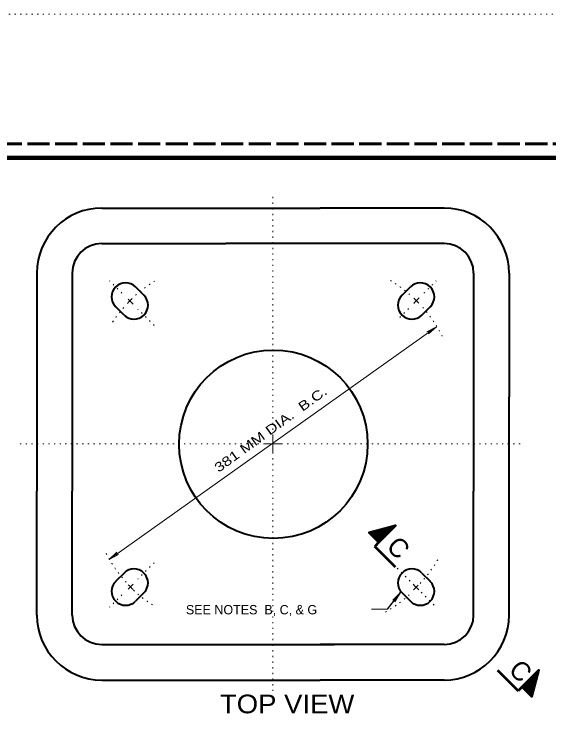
# Model space of a CAD drawing. Extents: x 312583 to 312854, y 144419 to 144597.
# Drawn here: x 312713.9 to 312757.4, y 144539.3 to 144596.8 of the extents above; entities that cross this region are included whole.
import ezdxf
from ezdxf.enums import TextEntityAlignment as Align

# ---------------------------------------------------------------- set-up
doc = ezdxf.new("R2010")
doc.units = 0
doc.header["$LTSCALE"] = 0.3
doc.linetypes.add('DOTTED', pattern=[1.5, 0.3, -1.2])
doc.linetypes.add('LONG_DASHED', pattern=[7.5, 6, -1.5])
for name, color, linetype, lineweight in [('1', 7, 'Continuous', 40), ('2', 7, 'Continuous', 13), ('62', 7, 'DOTTED', 13), ('63', 7, 'LONG_DASHED', 60)]:
    doc.layers.add(name, color=color, linetype=linetype, lineweight=lineweight)

msp = doc.modelspace()

# ---------------------------------------------------------------- linework, layer by layer
at = {"layer": '1'}
for p, q in [((312721.0029, 144581.0012), (312738.7589, 144581.0012)), ((312748.8483, 144581.0012), (312738.7589, 144581.0012)), ((312721.0029, 144578.1186), (312731.0923, 144578.1186)), ((312748.8483, 144578.1186), (312731.0923, 144578.1186)), ((312715.7206, 144575.7112), (312715.7206, 144557.9629)), ((312718.6033, 144575.7112), (312718.6033, 144557.9629)), ((312751.2479, 144575.7112), (312751.2479, 144557.9629)), ((312754.1306, 144575.7112), (312754.1306, 144565.6296)), ((312724.4299, 144573.9096), (312723.7476, 144574.5842)), ((312745.4289, 144573.9096), (312746.1036, 144574.5842)), ((312722.8123, 144572.2919), (312722.1376, 144572.9666)), ((312747.0389, 144572.2919), (312747.7213, 144572.9666)), ((312754.1306, 144547.8736), (312754.1306, 144565.6296)), ((312715.7206, 144547.8736), (312715.7206, 144557.9629)), ((312718.6033, 144547.8736), (312718.6033, 144557.9629)), ((312751.2479, 144547.8736), (312751.2479, 144557.9629)), ((312722.8123, 144551.2929), (312722.1376, 144550.6182)), ((312747.0389, 144551.2929), (312747.7213, 144550.6182)), ((312724.4299, 144549.6829), (312723.7476, 144549.0006)), ((312745.4289, 144549.6829), (312746.1036, 144549.0006)), ((312721.0029, 144545.4662), (312739.9396, 144545.4662)), ((312748.8483, 144545.4662), (312738.7589, 144545.4662)), ((312721.0029, 144542.5836), (312738.7589, 144542.5836)), ((312748.8483, 144542.5836), (312738.7589, 144542.5836))]:
    msp.add_line(p, q, dxfattribs=at)
at = {"layer": '1', "linetype": 'DOTTED', "lineweight": 13}
for p, q in [((312722.6436, 144574.0782), (312721.6393, 144575.0749)), ((312747.1999, 144574.0629), (312748.2119, 144575.0749)), ((312746.3719, 144573.2349), (312746.8703, 144573.7409)), ((312745.2373, 144572.1002), (312746.1189, 144572.9819)), ((312725.2733, 144571.4486), (312723.9316, 144572.7826)), ((312725.2733, 144552.1362), (312723.9316, 144550.8022)), ((312745.0379, 144551.6839), (312748.2119, 144548.5099)), ((312722.6436, 144549.5066), (312721.6393, 144548.5099))]:
    msp.add_line(p, q, dxfattribs=at)
at = {"layer": '1', "lineweight": 13}
for p, q in [((312723.5483, 144573.1736), (312723.1419, 144573.5799)), ((312746.4103, 144573.2809), (312746.8243, 144573.6872)), ((312723.5483, 144550.3882), (312723.1419, 144549.9819)), ((312746.3796, 144550.3192), (312746.7859, 144549.9129))]:
    msp.add_line(p, q, dxfattribs=at)
at = {"layer": '1', "lineweight": 35}
for p, q in [((312744.6929, 144554.9422), (312744.6469, 144555.0879)), ((312744.7083, 144554.9576), (312744.6776, 144555.0956)), ((312744.7236, 144554.9806), (312744.6929, 144555.0956)), ((312744.7466, 144554.9959), (312744.7236, 144555.1032)), ((312744.7696, 144555.0189), (312744.7389, 144555.1109)), ((312744.7926, 144555.0419), (312744.7696, 144555.1186)), ((312744.8079, 144555.0572), (312744.7849, 144555.1186)), ((312744.8233, 144555.0802), (312744.8079, 144555.1339)), ((312744.8463, 144555.0956), (312744.8309, 144555.1416)), ((312744.8693, 144555.1186), (312744.8539, 144555.1416)), ((312744.8923, 144555.1339), (312744.8769, 144555.1492)), ((312742.7763, 144554.5589), (312742.7763, 144554.5819)), ((312742.8146, 144554.5282), (312742.7993, 144554.5896)), ((312742.8529, 144554.4899), (312742.8299, 144554.5896)), ((312742.8836, 144554.4516), (312742.8529, 144554.5972)), ((312742.9219, 144554.4209), (312742.8683, 144554.6049)), ((312742.9449, 144554.3902), (312742.8913, 144554.6049)), ((312742.9909, 144554.3519), (312742.9143, 144554.6202)), ((312743.0216, 144554.3212), (312742.9449, 144554.6279)), ((312743.0523, 144554.2906), (312742.9603, 144554.6356)), ((312743.0829, 144554.2599), (312742.9909, 144554.6432)), ((312743.1213, 144554.2139), (312743.0063, 144554.6432)), ((312743.1519, 144554.1832), (312743.0369, 144554.6509)), ((312743.1826, 144554.1526), (312743.0523, 144554.6586)), ((312743.2286, 144554.1142), (312743.0753, 144554.6586)), ((312743.2593, 144554.0836), (312743.0983, 144554.6739)), ((312743.2899, 144554.0529), (312743.1136, 144554.6739)), ((312743.3283, 144554.0069), (312743.1443, 144554.6739)), ((312743.3589, 144553.9839), (312743.1749, 144554.6892)), ((312743.3973, 144553.9456), (312743.1903, 144554.6892)), ((312743.4203, 144553.9149), (312743.2133, 144554.6969)), ((312743.4586, 144553.8766), (312743.2439, 144554.7046)), ((312743.4893, 144553.8459), (312743.2593, 144554.7046)), ((312743.5276, 144553.8152), (312743.2899, 144554.7199)), ((312743.5506, 144553.8076), (312743.3053, 144554.7199)), ((312743.5736, 144553.8306), (312743.3359, 144554.7352)), ((312743.5966, 144553.8459), (312743.3589, 144554.7352)), ((312743.6119, 144553.8612), (312743.3743, 144554.7429)), ((312743.6349, 144553.8842), (312743.3973, 144554.7429)), ((312743.6426, 144553.9072), (312743.4279, 144554.7582)), ((312743.6733, 144553.9302), (312743.4509, 144554.7582)), ((312743.6886, 144553.9456), (312743.4663, 144554.7736)), ((312743.7116, 144553.9609), (312743.4969, 144554.7736)), ((312743.7346, 144553.9839), (312743.5199, 144554.7736)), ((312743.7499, 144553.9992), (312743.5353, 144554.7889)), ((312743.7729, 144554.0222), (312743.5659, 144554.7889)), ((312743.7883, 144554.0452), (312743.5889, 144554.7966)), ((312743.8036, 144554.0606), (312743.6119, 144554.8042)), ((312743.8266, 144554.0836), (312743.6349, 144554.8042)), ((312743.8496, 144554.1066), (312743.6579, 144554.8196)), ((312743.8649, 144554.1219), (312743.6809, 144554.8196)), ((312743.8879, 144554.1372), (312743.7039, 144554.8272)), ((312743.9033, 144554.1602), (312743.7346, 144554.8349)), ((312743.9263, 144554.1756), (312743.7423, 144554.8426)), ((312743.9493, 144554.2062), (312743.7729, 144554.8502)), ((312743.9646, 144554.2216), (312743.7959, 144554.8579)), ((312743.9876, 144554.2369), (312743.8113, 144554.8579)), ((312744.0029, 144554.2599), (312743.8419, 144554.8732)), ((312744.0259, 144554.2752), (312743.8649, 144554.8732)), ((312744.0413, 144554.2906), (312743.8879, 144554.8809)), ((312744.0566, 144554.3136), (312743.9109, 144554.8886)), ((312744.0873, 144554.3366), (312743.9339, 144554.8886)), ((312744.1026, 144554.3519), (312743.9569, 144554.8962)), ((312744.1179, 144554.3749), (312743.9799, 144554.9039)), ((312744.1409, 144554.3979), (312744.0029, 144554.9116)), ((312744.1563, 144554.4132), (312744.0259, 144554.9116)), ((312744.1869, 144554.4362), (312744.0489, 144554.9269)), ((312744.2023, 144554.4516), (312744.0719, 144554.9269)), ((312744.2176, 144554.4746), (312744.0949, 144554.9346)), ((312744.2329, 144554.4899), (312744.1179, 144554.9499)), ((312744.2636, 144554.5129), (312744.1409, 144554.9576)), ((312744.2789, 144554.5282), (312744.1639, 144554.9576)), ((312744.3019, 144554.5589), (312744.1869, 144554.9576)), ((312744.3173, 144554.5666), (312744.2099, 144554.9729)), ((312744.3403, 144554.5896), (312744.2329, 144554.9652)), ((312744.3556, 144554.6126), (312744.2636, 144554.9729)), ((312744.3786, 144554.6279), (312744.2789, 144554.9882)), ((312744.3939, 144554.6432), (312744.3019, 144554.9882)), ((312744.4169, 144554.6662), (312744.3249, 144554.9959)), ((312744.4399, 144554.6892), (312744.3556, 144555.0036)), ((312744.4553, 144554.7046), (312744.3633, 144555.0112)), ((312744.4706, 144554.7276), (312744.4016, 144555.0189)), ((312744.4936, 144554.7429), (312744.4169, 144555.0266)), ((312744.5166, 144554.7659), (312744.4399, 144555.0342)), ((312744.5319, 144554.7889), (312744.4629, 144555.0419)), ((312744.5549, 144554.8042), (312744.4859, 144555.0419)), ((312744.5703, 144554.8196), (312744.5089, 144555.0496)), ((312744.5933, 144554.8426), (312744.5319, 144555.0572)), ((312744.6086, 144554.8656), (312744.5549, 144555.0572)), ((312744.6316, 144554.8886), (312744.5779, 144555.0649)), ((312744.6623, 144554.9039), (312744.6086, 144555.0726)), ((312744.6699, 144554.9192), (312744.6239, 144555.0726)), ((312756.2006, 144543.0282), (312756.4536, 144542.9592)), ((312756.2159, 144543.0436), (312756.4536, 144542.9822)), ((312756.2389, 144543.0666), (312756.4613, 144543.0052)), ((312756.2543, 144543.0819), (312756.4689, 144543.0282)), ((312756.2773, 144543.1049), (312756.4689, 144543.0512)), ((312756.2926, 144543.1279), (312756.4766, 144543.0742)), ((312756.3156, 144543.1509), (312756.4843, 144543.0972)), ((312756.3309, 144543.1662), (312756.4843, 144543.1202)), ((312756.3539, 144543.1892), (312756.4919, 144543.1432)), ((312756.3693, 144543.2046), (312756.4996, 144543.1739)), ((312756.3846, 144543.2199), (312756.5149, 144543.1892)), ((312756.4076, 144543.2429), (312756.5149, 144543.2122)), ((312756.4306, 144543.2659), (312756.5226, 144543.2352)), ((312756.4536, 144543.2812), (312756.5303, 144543.2659)), ((312756.4689, 144543.3042), (312756.5379, 144543.2812)), ((312756.4919, 144543.3196), (312756.5379, 144543.3042)), ((312756.5073, 144543.3349), (312756.5533, 144543.3272)), ((312756.5303, 144543.3579), (312756.5533, 144543.3502)), ((312756.5533, 144543.3809), (312756.5609, 144543.3732)), ((312755.6103, 144542.4456), (312756.2543, 144542.2616)), ((312755.6256, 144542.4609), (312756.2696, 144542.2846)), ((312755.6486, 144542.4839), (312756.2696, 144542.3076)), ((312755.6716, 144542.4916), (312756.2849, 144542.3382)), ((312755.6869, 144542.5222), (312756.2849, 144542.3536)), ((312755.7023, 144542.5376), (312756.2926, 144542.3842)), ((312755.7253, 144542.5606), (312756.3003, 144542.4072)), ((312755.7483, 144542.5759), (312756.3003, 144542.4302)), ((312755.7636, 144542.5989), (312756.3079, 144542.4532)), ((312755.7866, 144542.6142), (312756.3156, 144542.4762)), ((312755.8096, 144542.6372), (312756.3233, 144542.4916)), ((312755.8249, 144542.6526), (312756.3309, 144542.5222)), ((312755.8479, 144542.6756), (312756.3386, 144542.5452)), ((312755.8633, 144542.6986), (312756.3386, 144542.5606)), ((312755.8863, 144542.7139), (312756.3463, 144542.5836)), ((312755.9016, 144542.7292), (312756.3539, 144542.6142)), ((312755.9246, 144542.7522), (312756.3616, 144542.6372)), ((312755.9399, 144542.7752), (312756.3693, 144542.6526)), ((312755.9629, 144542.7982), (312756.3693, 144542.6832)), ((312755.9783, 144542.8136), (312756.3846, 144542.7062)), ((312756.0013, 144542.8366), (312756.3846, 144542.7292)), ((312756.0166, 144542.8519), (312756.3846, 144542.7522)), ((312756.0396, 144542.8749), (312756.3999, 144542.7752)), ((312756.0549, 144542.8902), (312756.3999, 144542.7982)), ((312756.0779, 144542.9132), (312756.4076, 144542.8212)), ((312756.1009, 144542.9286), (312756.4153, 144542.8442)), ((312756.1163, 144542.9516), (312756.4229, 144542.8596)), ((312756.1393, 144542.9669), (312756.4306, 144542.8902)), ((312756.1546, 144542.9899), (312756.4383, 144542.9132)), ((312756.1776, 144543.0052), (312756.4383, 144542.9362)), ((312755.2193, 144542.0469), (312756.1316, 144541.8016)), ((312755.2193, 144542.0239), (312756.1316, 144541.7862)), ((312755.2346, 144542.0699), (312756.1469, 144541.8246)), ((312755.2576, 144542.0929), (312756.1469, 144541.8552)), ((312755.2576, 144541.9856), (312756.1163, 144541.7556)), ((312755.2729, 144542.1082), (312756.1546, 144541.8706)), ((312755.2883, 144541.9549), (312756.1163, 144541.7326)), ((312755.2959, 144542.1312), (312756.1623, 144541.8936)), ((312755.3189, 144542.1389), (312756.1699, 144541.9166)), ((312755.3266, 144541.9166), (312756.1086, 144541.7096)), ((312755.3419, 144542.1619), (312756.1699, 144541.9396)), ((312755.3496, 144542.1849), (312756.1776, 144541.9626)), ((312755.3573, 144541.8859), (312756.1009, 144541.6866)), ((312755.3726, 144542.2079), (312756.1853, 144541.9856)), ((312755.3956, 144542.2309), (312756.1853, 144542.0086)), ((312755.4109, 144542.2462), (312756.2006, 144542.0316)), ((312755.4339, 144542.2616), (312756.2006, 144542.0622)), ((312755.4569, 144542.2846), (312756.2083, 144542.0852)), ((312755.4723, 144542.2999), (312756.2159, 144542.1006)), ((312755.4953, 144542.3229), (312756.2159, 144542.1312)), ((312755.5183, 144542.3459), (312756.2313, 144542.1542)), ((312755.5336, 144542.3612), (312756.2313, 144542.1696)), ((312755.5489, 144542.3766), (312756.2389, 144542.1926)), ((312755.5719, 144542.3996), (312756.2466, 144542.2232)), ((312755.5873, 144542.4226), (312756.2543, 144542.2386)), ((312755.3879, 144541.8552), (312756.1009, 144541.6636)), ((312755.4186, 144541.8169), (312756.0933, 144541.6406)), ((312755.4569, 144541.7862), (312756.0856, 144541.6176)), ((312755.4953, 144541.7479), (312756.0856, 144541.5946)), ((312755.5259, 144541.7172), (312756.0703, 144541.5716)), ((312755.5643, 144541.6789), (312756.0703, 144541.5486)), ((312755.5949, 144541.6482), (312756.0626, 144541.5256)), ((312755.6256, 144541.6176), (312756.0549, 144541.5026)), ((312755.6639, 144541.5792), (312756.0549, 144541.4872)), ((312755.7023, 144541.5409), (312756.0396, 144541.4489)), ((312755.7329, 144541.5102), (312756.0319, 144541.4336)), ((312755.7636, 144541.4796), (312756.0319, 144541.4106)), ((312755.8019, 144541.4412), (312756.0166, 144541.3876)), ((312755.8326, 144541.4106), (312756.0166, 144541.3646)), ((312755.8633, 144541.3722), (312756.0089, 144541.3416)), ((312755.9016, 144541.3416), (312756.0013, 144541.3186)), ((312755.9399, 144541.3032), (312756.0013, 144541.2956)), ((312755.9706, 144541.2726), (312755.9936, 144541.2726))]:
    msp.add_line(p, q, dxfattribs=at)
at = {"layer": '1', "lineweight": 53}
for p, q in [((312743.5429, 144553.7999), (312743.2056, 144553.4549)), ((312744.8923, 144551.7682), (312743.2056, 144553.4549)), ((312753.1799, 144543.3962), (312754.8666, 144541.7019)), ((312755.2039, 144542.0392), (312754.8666, 144541.7019))]:
    msp.add_line(p, q, dxfattribs=at)
at = {"layer": '1', "lineweight": 158}
msp.add_lwpolyline([(312616.5, 144423.1446), (312616.5, 144585.0846), (312849, 144585.0846)], dxfattribs=at)
at = {"layer": '1', "lineweight": 53}
for points in [[(312743.5429, 144553.7999), (312742.7533, 144554.5819), (312744.8999, 144555.1492)], [(312755.2039, 144542.0392), (312755.9936, 144541.2496), (312756.5609, 144543.3962)]]:
    msp.add_lwpolyline(points, close=True, dxfattribs=at)
at = {"layer": '1'}
msp.add_circle((312734.9574, 144561.7774), 7.6667, dxfattribs=at)
for centre, radius, start, end in [((312721.005, 144575.7135), 5.2842, 90, 180), ((312748.8478, 144575.7135), 5.2842, 0, 90), ((312721.005, 144575.7135), 2.4019, 90, 180), ((312748.8478, 144575.7135), 2.4019, 0, 90), ((312722.9419, 144573.7766), 1.1413, 45, 225), ((312746.9109, 144573.7766), 1.1413, 315, 135), ((312723.6202, 144573.0983), 1.1413, 225, 45), ((312746.2326, 144573.0983), 1.1413, 135, 315), ((312723.6202, 144550.4859), 1.1413, 315, 135), ((312746.2326, 144550.4859), 1.1413, 45, 225), ((312722.9419, 144549.8076), 1.1413, 135, 315), ((312746.9109, 144549.8076), 1.1413, 225, 45), ((312721.005, 144547.8707), 5.2842, 180, 270), ((312721.005, 144547.8707), 2.4019, 180, 270), ((312748.8478, 144547.8707), 5.2842, 270, 0), ((312748.8478, 144547.8707), 2.4019, 270, 0)]:
    msp.add_arc(centre, radius, start, end, dxfattribs=at)
at = {"layer": '1', "linetype": 'DOTTED', "lineweight": 13}
for centre, start, end in [((312738.5144, 144565.2287), 49.22437, 60.18147), ((312731.3729, 144565.2536), 121.71451, 131.36639), ((312731.4419, 144565.2766), 138.63519, 147.17965), ((312738.4224, 144565.3341), 26.95504, 40.99668), ((312731.5358, 144558.2846), 207.95114, 222.81842), ((312738.4339, 144558.2846), 317.18755, 330.45291), ((312731.4419, 144558.3325), 227.09361, 238.28549), ((312738.34, 144558.1217), 299.81853, 312.90541)]:
    msp.add_arc(centre, 11.5292, start, end, dxfattribs=at)
at = {"layer": '1', "lineweight": 13}
for centre, start, end in [((312731.4419, 144565.2996), 133.65585, 136.45218), ((312738.4339, 144565.3111), 43.54782, 46.34415), ((312731.5109, 144558.2846), 223.54782, 226.34415), ((312738.386, 144558.2616), 313.65585, 316.45218)]:
    msp.add_arc(centre, 11.5292, start, end, dxfattribs=at)
at = {"layer": '2', "linetype": 'DOTTED'}
for p, q in [((312734.9256, 144562.9462), (312734.9256, 144581.9979)), ((312733.7756, 144561.7962), (312714.2869, 144561.7962)), ((312733.7756, 144561.7962), (312732.6946, 144561.7962)), ((312736.0756, 144561.7962), (312755.1503, 144561.7962)), ((312734.9256, 144560.6462), (312734.9256, 144541.6942)), ((312734.9256, 144560.6386), (312734.9256, 144560.1249))]:
    msp.add_line(p, q, dxfattribs=at)
at = {"layer": '2'}
for p, q in [((312721.5933, 144552.3969), (312748.2196, 144571.3412)), ((312748.2196, 144571.3412), (312747.4529, 144570.9272)), ((312748.2196, 144571.3412), (312747.4529, 144570.9272)), ((312748.2196, 144571.3412), (312747.5756, 144570.7509)), ((312748.2196, 144571.3412), (312747.5756, 144570.7509)), ((312747.4529, 144570.9272), (312747.7366, 144571.0039)), ((312747.4529, 144570.9272), (312747.7366, 144571.0039)), ((312747.5756, 144570.7509), (312747.7366, 144571.0039)), ((312747.5756, 144570.7509), (312747.7366, 144571.0039)), ((312734.9256, 144561.7962), (312734.9256, 144562.5629)), ((312734.9256, 144561.7962), (312734.1589, 144561.7962)), ((312734.9256, 144561.7962), (312734.1589, 144561.7962)), ((312734.9256, 144561.7962), (312734.9256, 144561.0219)), ((312734.9256, 144561.7962), (312735.6923, 144561.7962)), ((312734.9256, 144561.7962), (312734.9256, 144561.0296)), ((312721.5933, 144552.3969), (312722.2373, 144552.9872)), ((312721.5933, 144552.3969), (312722.3676, 144552.8109)), ((312722.2373, 144552.9872), (312722.0763, 144552.7419)), ((312722.3676, 144552.8109), (312722.0763, 144552.7419)), ((312745.2909, 144549.6982), (312744.6776, 144549.0772)), ((312745.2909, 144549.6982), (312744.8463, 144548.9469)), ((312744.6776, 144549.0772), (312744.9306, 144549.2306)), ((312744.8463, 144548.9469), (312744.9306, 144549.2306)), ((312742.9373, 144548.3412), (312744.2483, 144548.3412))]:
    msp.add_line(p, q, dxfattribs=at)
at = {"layer": '2', "lineweight": 25}
msp.add_line((312744.2483, 144548.3412), (312745.2909, 144549.6982), dxfattribs=at)
at = {"layer": '62'}
msp.add_line((312601.2, 144596.7846), (312853.5, 144596.7846), dxfattribs=at)
at = {"layer": '63'}
msp.add_line((312851.75, 144586.2246), (312583.526, 144586.2246), dxfattribs=at)

# ---------------------------------------------------------------- texts
at = {"layer": '1'}
for p in [(312744.586, 144552.8182), (312754.5296, 144542.7825)]:
    msp.add_text('C', height=1.533, rotation=315, dxfattribs=at).set_placement(p, align=Align.CENTER)
at = {"layer": '2', "width": 1.3}
msp.add_text('381 MM DIA.  B.C.', height=0.76, rotation=36, dxfattribs=at).set_placement((312730.5031, 144559.446))
at = {"layer": '2'}
msp.add_text('SEE NOTES  B, C, & G', height=0.76, dxfattribs=at).set_placement((312727.8455, 144547.9281))
at = {"layer": '2', "width": 1.1}
msp.add_text('TOP VIEW', height=1.52, dxfattribs=at).set_placement((312730.6126, 144539.8785))

doc.saveas('drawing.dxf')
